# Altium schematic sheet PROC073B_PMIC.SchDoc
size 431 x 279 mm; Date: Not shown in title block; ApprovedBy: Not shown in title block; CheckedBy: Not shown in title block; Author: Not shown in title block; CompanyName: Not shown in title block; Engineer: Not shown in title block; Organization: Not shown in title block; Address1: Not shown in title block; Address2: Not shown in title block; Address3: Not shown in title block; Address4: Not shown in title block; DocumentNumber: 1; Revision: Use project parameter SCH_Rev; SheetNumber: 3; SheetTotal: 9; PageSetup: Record=PageOptions¦CenterHorizontal=True¦CenterVertical=True¦PrintScale=1.00¦XCorrection=1.00¦YCorrection=1.00¦PrintKind=0¦BorderSize=5000000¦LeftOffset=0¦BottomOffset=0¦Orientation=2¦PaperLength=1000¦PaperWidth=1000¦Scale=100¦PaperSource=15¦PrintQuality=600¦MediaType=1¦DitherType=10¦PaperKind=Letter¦PrintScaleMode=1
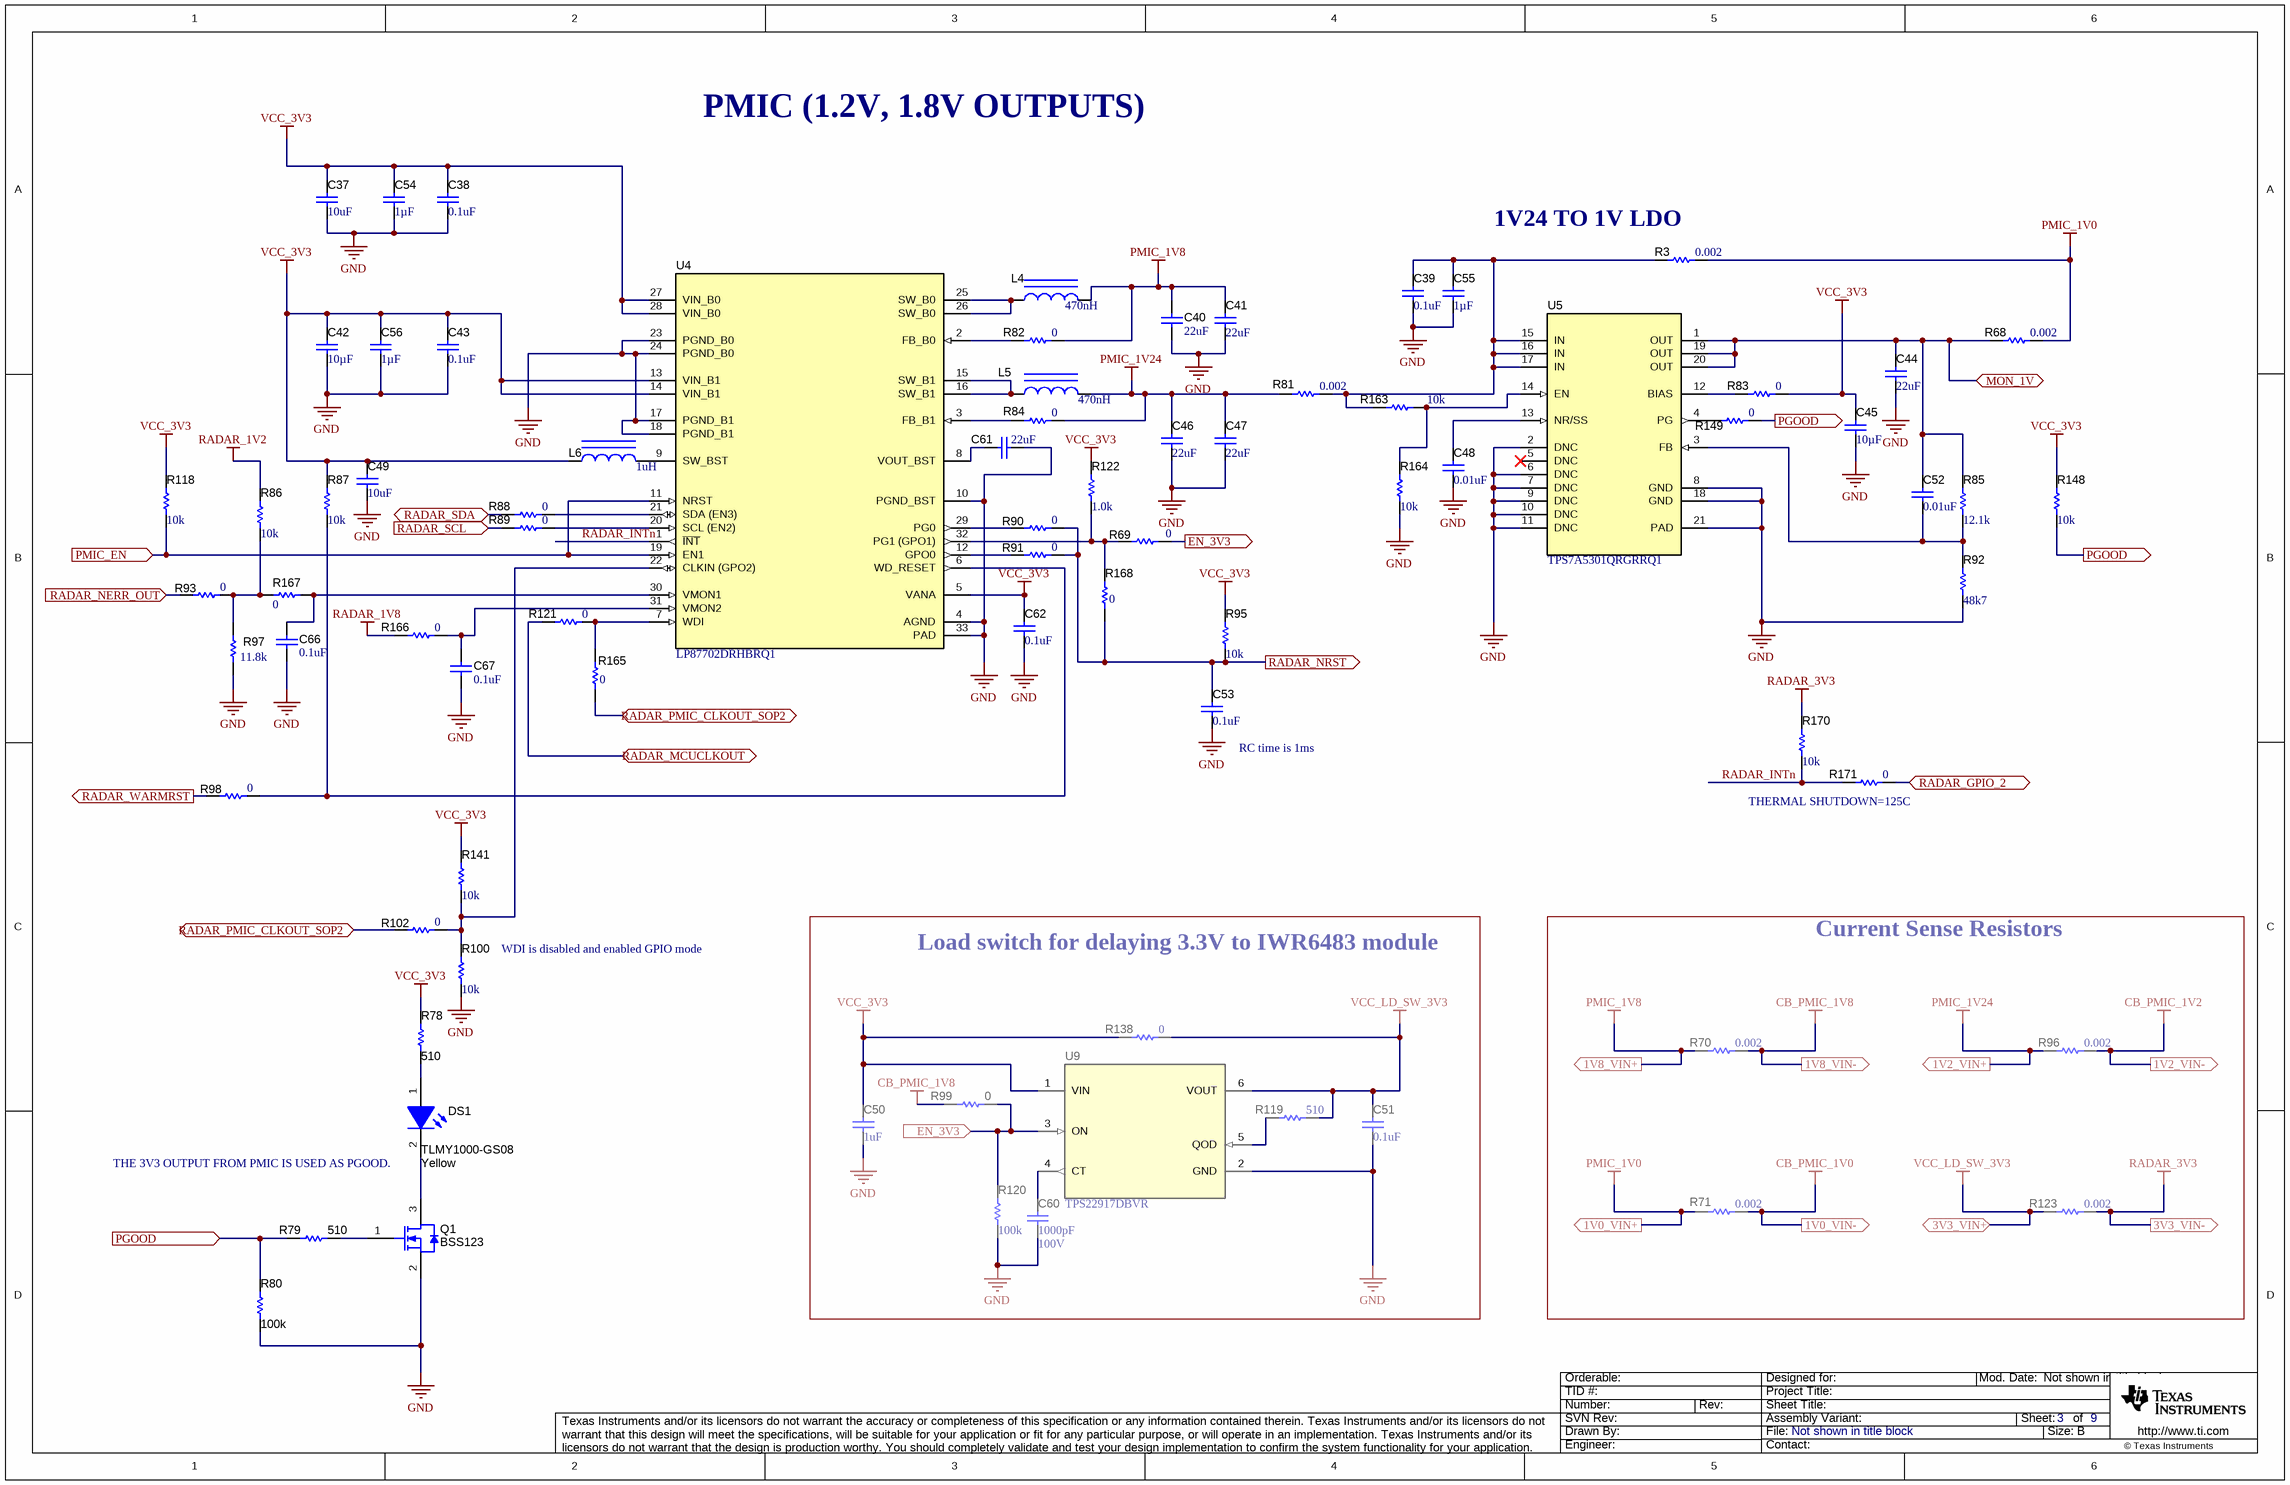
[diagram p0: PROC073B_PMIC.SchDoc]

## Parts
C37  value 10uF  [0805_HV]  (hidden comment: CL21B106KOQNNNE)
C38  value 0.1uF  [0402]  (hidden comment: 0402YC104KAT2A)
C39  ValueDisplayed: 0.1uF  [0402]  (hidden comment: 0402YC104KAT2A)
C40  ValueDisplayed: 22uF  [0805]  (hidden comment: GRM21BD70J226ME44L)
C41  ValueDisplayed: 22uF  [0805]  (hidden comment: GRM21BD70J226ME44L)
C42  Cap_F: 10µF  [0805_HV1]  (hidden comment: CL21B106KOQNNNE)
C43  value 0.1uF  [0402]  (hidden comment: 0402YC104KAT2A)
C44  ValueDisplayed: 22uF  [0805_HV]  (hidden comment: GRM21BD70J226ME44L)
C45  ValueDisplayed: 10µF  [0805_HV]  (hidden comment: GRM21BR71A106KA73L)
C46  ValueDisplayed: 22uF  [0805]  (hidden comment: GRM21BD70J226ME44L)
C47  ValueDisplayed: 22uF  [0805]  (hidden comment: GRM21BD70J226ME44L)
C48  ValueDisplayed: 0.01uF  [0402]  (hidden comment: GRM155R71C103KA01D)
C49  value 10uF  [0805_HV1]  (hidden comment: CL21B106KOQNNNE)
C50  ValueDisplayed: 1uF  [0603]  (hidden comment: CL10B105KQ8NNNC)
C51  ValueDisplayed: 0.1uF  [0603]  (hidden comment: GRM188R70J104KA01D)
C52  ValueDisplayed: 0.01uF  [0402]  (hidden comment: GRM155R71C103KA01D)
C53  ValueDisplayed: 0.1uF  [0402]  (hidden comment: 0402YC104KAT2A)
C54  ValueDisplayed: 1µF  [0402]  (hidden comment: CGB2A1X6S0J105K033BC)
C55  ValueDisplayed: 1µF  [0402]  (hidden comment: CGB2A1X6S0J105K033BC)
C56  ValueDisplayed: 1µF  [0402]  (hidden comment: CGB2A1X6S0J105K033BC)
C60  VDC_V: 100V  ValueDisplayed: 1000pF  [0402]  (hidden comment: CGA2B3X7S2A102K050BB)
C61  ValueDisplayed: 22uF  [0805_HV]  (hidden comment: GRM219R61C226ME15L)
C62  value 0.1uF  [0402]  (hidden comment: 0402YC104KAT2A)
C66  ValueDisplayed: 0.1uF  [0402]  (hidden comment: 0402YC104KAT2A)
C67  ValueDisplayed: 0.1uF  [0402]  (hidden comment: 0402YC104KAT2A)
DS1  TLMY1000-GS08  value Yellow  [TLMx1000_Yellow]
L4  value 470nH  [DFE252012P]  (hidden comment: DFE252012PD-R47M)
L5  value 470nH  [DFE252012P]  (hidden comment: DFE252012PD-R47M)
L6  value 1uH  [DFE252012P]  (hidden comment: DFE252012PD-1R0M)
Q1  BSS123  [SOT-23]
R3  ValueDisplayed: 0.002  [1206]  (hidden comment: PMR18EZPFV2L00)
R68  ValueDisplayed: 0.002  [1206]  (hidden comment: PMR18EZPFV2L00)
R69  value 0  [0402]  (hidden comment: CRCW04020000Z0ED)
R70  ValueDisplayed: 0.002  [1206]  (hidden comment: PMR18EZPFV2L00)
R71  ValueDisplayed: 0.002  [1206]  (hidden comment: PMR18EZPFV2L00)
R78  ValueDisplayed: 510  [0402L]  (hidden comment: ERJ-2GEJ511X)
R79  ValueDisplayed: 510  [0402L]  (hidden comment: ERJ-2GEJ511X)
R80  ValueDisplayed: 100k  [0402L]  (hidden comment: CRCW0402100KFKED)
R81  ValueDisplayed: 0.002  [1206]  (hidden comment: PMR18EZPFV2L00)
R82  value 0  [0402]  (hidden comment: CRCW04020000Z0ED)
R83  ValueDisplayed: 0  [0402]  (hidden comment: CRCW04020000Z0ED)
R84  value 0  [0402]  (hidden comment: CRCW04020000Z0ED)
R85  value 12.1k  [0402]  (hidden comment: CRCW040212K1FKED)
R86  value 10k  [0402]  (hidden comment: CRCW040210K0JNED)
R87  value 10k  [0402]  (hidden comment: CRCW040210K0JNED)
R88  ValueDisplayed: 0  [0201]  (hidden comment: CRCW02010000Z0ED)
R89  ValueDisplayed: 0  [0201]  (hidden comment: CRCW02010000Z0ED)
R90  value 0  [0402]  (hidden comment: CRCW04020000Z0ED)
R91  value 0  [0402]  (hidden comment: CRCW04020000Z0ED)
R92  Value_Code: 48k7  [0402]  (hidden comment: CRCW040248K7FKED)
R93  Res_ohm: 0  [0402]  (hidden comment: CRCW04020000Z0ED)
R95  value 10k  [0402]  (hidden comment: CRCW040210K0JNED)
R96  ValueDisplayed: 0.002  [1206]  (hidden comment: PMR18EZPFV2L00)
R97  ValueDisplayed: 11.8k  [0402]  (hidden comment: CRCW040211K8FKED)
R98  ValueDisplayed: 0  [0402]  (hidden comment: CRCW04020000Z0ED)
R99  ValueDisplayed: 0  [0603]  (hidden comment: MCT06030Z0000ZP500)
R100  value 10k  [0402]  (hidden comment: CRCW040210K0JNED)
R102  value 0  [0402]  (hidden comment: CRCW04020000Z0ED)
R118  value 10k  [0402]  (hidden comment: CRCW040210K0JNED)
R119  ValueDisplayed: 510  [0402]  (hidden comment: CRCW0402510RJNED)
R120  ValueDisplayed: 100k  [0402]  (hidden comment: ERJ-2RKF1003X)
R121  Res_ohm: 0  [0402]  (hidden comment: CRCW04020000Z0ED)
R122  value 1.0k  [0603]  (hidden comment: RC0603JR-071KL)
R123  ValueDisplayed: 0.002  [1206]  (hidden comment: PMR18EZPFV2L00)
R138  ValueDisplayed: 0  [0603]  (hidden comment: RCS06030000Z0EA)
R141  value 10k  [0402]  (hidden comment: CRCW040210K0JNED)
R148  value 10k  [0402]  (hidden comment: CRCW040210K0JNED)
R149  ValueDisplayed: 0  [0201]  (hidden comment: CRCW02010000Z0ED)
R163  value 10k  [0402]  (hidden comment: CRCW040210K0JNED)
R164  value 10k  [0402]  (hidden comment: CRCW040210K0JNED)
R165  Res_ohm: 0  [0402]  (hidden comment: CRCW04020000Z0ED)
R166  Res_ohm: 0  [0402]  (hidden comment: CRCW04020000Z0ED)
R167  Res_ohm: 0  [0402]  (hidden comment: CRCW04020000Z0ED)
R168  value 0  [0402]  (hidden comment: CRCW04020000Z0ED)
R170  value 10k  [0402]  (hidden comment: CRCW040210K0JNED)
R171  Res_ohm: 0  [0402]  (hidden comment: CRCW04020000Z0ED)
U4  LP87702DRHBRQ1  [RHB0032N]
U5  TPS7A5301QRGRRQ1  [RGR0020A]
U9  TPS22917DBVR  [DBV0006A_N]

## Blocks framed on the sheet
Load switch for delaying 3.3V to IWR6483 module: C50 C51 C60 R99 R119 R120 R138 U9
Current Sense Resistors: R70 R71 R96 R123

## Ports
1V0_VIN+ (out), 1V0_VIN- (out), 1V2_VIN+ (out), 1V2_VIN- (out), 1V8_VIN+ (out), 1V8_VIN- (out), 3V3_VIN+, 3V3_VIN- (out), EN_3V3 (in), EN_3V3 (out), MON_1V, PGOOD (in), PGOOD (out), PMIC_EN (in), RADAR_GPIO_2 (bidir), RADAR_MCUCLKOUT, RADAR_NERR_OUT (in), RADAR_NRST (out), RADAR_PMIC_CLKOUT_SOP2, RADAR_SCL (in), RADAR_SDA (bidir), RADAR_WARMRST (out)

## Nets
CB_PMIC_1V0: R71.2 ; port 1V0_VIN-
CB_PMIC_1V2: R96.2 ; port 1V2_VIN-
CB_PMIC_1V8: R70.2 R99.1 ; port 1V8_VIN-
GND: C37.1 C38.1 C39.1 C40.1 C41.2 C42.2 C43.1 C44.2 C45.1 C46.2 C47.2 C48.1 C49.2 C50.2 C51.2 C53.1 C54.2 C55.2 C56.2 C60.2 C61.2 C62.1 C66.1 C67.1 Q1.2(S) R80.1 R92.1 R97.2 R100.1 R120.1 R164.1 U4.4(AGND) U4.10(PGND_BST) U4.17(PGND_B1) U4.18(PGND_B1) U4.23(PGND_B0) U4.24(PGND_B0) U4.33(PAD) U5.2(DNC) U5.6(DNC) U5.7(DNC) U5.8(GND) U5.9(DNC) U5.10(DNC) U5.11(DNC) U5.18(GND) U5.21(PAD) U9.2(GND)
PMIC_1V0: R3.2 R68.2 R71.1 ; port 1V0_VIN+
PMIC_1V8: C40.2 C41.1 L4.2 R70.1 R82.2 ; port 1V8_VIN+
PMIC_1V24: C46.1 C47.1 L5.2 R81.1 R84.2 R96.1 ; port 1V2_VIN+
RADAR_1V2: R86.2
RADAR_1V8: R166.1
RADAR_3V3: R123.2 R170.2 ; port 3V3_VIN-
VCC_3V3: C37.2 C38.2 C42.1 C43.2 C45.2 C49.1 C50.1 C54.1 C56.1 C62.2 L6.1 R78.2 R83.2 R87.2 R95.2 R118.2 R122.1 R138.1 R141.2 R148.2 U4.5(VANA) U4.13(VIN_B1) U4.14(VIN_B1) U4.27(VIN_B0) U4.28(VIN_B0) U9.1(VIN)
VCC_LD_SW_3V3: C51.1 R119.1 R123.1 R138.2 U9.6(VOUT) ; port 3V3_VIN+
EN_3V3: R69.2 R99.2 R120.2 U9.3(ON) ; port EN_3V3
MON_1V: C44.1 C52.1 R68.1 R85.2 U5.1(OUT) U5.19(OUT) U5.20(OUT) ; port MON_1V
PGOOD: R79.1 R80.2 R148.1 R149.2 ; port PGOOD
PMIC_EN: R118.1 U4.11(NRST) U4.19(EN1) ; port PMIC_EN
RADAR_GPIO_2: R171.2 ; port RADAR_GPIO_2
RADAR_INTn: R170.1 R171.1 U4.1(~{INT})
RADAR_MCUCLKOUT: R121.1 ; port RADAR_MCUCLKOUT
RADAR_NERR_OUT: R93.1 ; port RADAR_NERR_OUT
RADAR_NRST: C53.2 R90.2 R91.2 R95.1 R168.1 ; port RADAR_NRST
RADAR_PMIC_CLKOUT_SOP2: R102.1 R165.1 ; port RADAR_PMIC_CLKOUT_SOP2
RADAR_SCL: R89.1 ; port RADAR_SCL
RADAR_SDA: R88.1 ; port RADAR_SDA
RADAR_WARMRST: R98.1 ; port RADAR_WARMRST
NetC39_2: C39.2 C55.1 R3.1 R81.2 R163.2 U5.15(IN) U5.16(IN) U5.17(IN)
NetC48_2: C48.2 U5.13(NR/SS)
NetC52_2: C52.2 R85.1 R92.2 U5.3(FB)
NetC60_1: C60.1 U9.4(CT)
NetC61_1: C61.1 U4.8(VOUT_BST)
NetC66_2: C66.2 R167.2 U4.30(VMON1)
NetC67_2: C67.2 R166.2 U4.31(VMON2)
NetDS1_1: DS1.1(A) R78.1
NetDS1_2: DS1.2(K) Q1.3(D)
NetL4_1: L4.1 U4.25(SW_B0) U4.26(SW_B0)
NetL5_1: L5.1 U4.15(SW_B1) U4.16(SW_B1)
NetL6_2: L6.2 U4.9(SW_BST)
NetQ1_1: Q1.1(G) R79.2
NetR69_1: R69.1 R122.2 R168.2 U4.32(PG1_(GPO1))
NetR82_1: R82.1 U4.2(FB_B0)
NetR83_1: R83.1 U5.12(BIAS)
NetR84_1: R84.1 U4.3(FB_B1)
NetR86_1: R86.1 R93.2 R97.1 R167.1
NetR87_1: R87.1 R98.2 U4.6(WD_RESET)
NetR88_2: R88.2 U4.21(SDA_(EN3))
NetR89_2: R89.2 U4.20(SCL_(EN2))
NetR90_1: R90.1 U4.29(PG0)
NetR91_1: R91.1 U4.12(GPO0)
NetR100_2: R100.2 R102.2 R141.1 U4.22(CLKIN_(GPO2))
NetR119_2: R119.2 U9.5(QOD)
NetR121_2: R121.2 R165.2 U4.7(WDI)
NetR149_1: R149.1 U5.4(PG)
NetR163_1: R163.1 R164.2 U5.14(EN)

Not connected (* = marked no-connect by the designer): U5 5(DNC)*

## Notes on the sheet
- PMIC (1.2V, 1.8V OUTPUTS)
- (near R3) 1V24 TO 1V LDO
- (near C53) RC time is 1ms
- (near R171) THERMAL SHUTDOWN=125C
- (near R100) WDI is disabled and enabled GPIO mode
- THE 3V3 OUTPUT FROM PMIC IS USED AS PGOOD.

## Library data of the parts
C37 C49 = CMP-0007995-2: CAP, CERM, 10 uF, 16 V, +/- 10%, X7R, 0805; Manufacturer: Samsung Electro-Mechanics; TaMin_C: -55°C; Polarized: N; SizeAreaWB_mm2: 6.75; Value1: Unknown; U/M: EA; TaMax_C: 125°C; SizeZ_mm: 1.45; SizeX_mm: 2; SizeY_mm: 1.25; Cap_Case: 0805; Value2: 16V; SizeArea_mm2: 2.5; CompType: Capacitor; Cap_F: 10µF; AEC Category: Q200
C38 C43 C62 = CMP-0006201-2: CAP, CERM, 0.1 uF, 16 V, +/- 10%, X7R, 0402; Manufacturer: AVX; TaMin_C: -55°C; Polarized: N; SizeAreaWB_mm2: 3; Value1: Unknown; U/M: EA; TaMax_C: 125°C; SizeZ_mm: 0.6; SizeX_mm: 1; SizeY_mm: 0.5; Value2: 16V; CompType: Capacitor; Cap_F: 100nF; AEC Category: Q200
C39 C53 C66 C67 = CMP-0006201-2: CAP, CERM, 0.1 uF, 16 V, +/- 10%, X7R, 0402; Manufacturer: AVX; TaMin_C: -55°C; Polarized: N; SizeAreaWB_mm2: 3; Value1: Unknown; U/M: EA; Value: 0.1uF; TaMax_C: 125°C; SizeZ_mm: 0.6; SizeX_mm: 1; SizeY_mm: 0.5; Value2: 16V; CompType: Capacitor; Cap_F: 100nF; AEC Category: Q200
C40 C41 C46 C47 = CMP-0008274-1: CAP, CERM, 22 uF, 6.3 V, +/- 20%, X7T, 0805; Manufacturer: MuRata; TaMin_C: -55°C; Polarized: N; SizeAreaWB_mm2: 6.75; Value1: Unknown; U/M: EA; Value: 22uF; TaMax_C: 125°C; SizeZ_mm: 1.45; SizeX_mm: 2; SizeY_mm: 1.25; Value2: 6.3V; SizeArea_mm2: 2.5; CompType: Capacitor; Cap_F: 22µF; AEC Category: Q200
C42 = CMP-0007995-2: CAP, CERM, 10 uF, 16 V, +/- 10%, X7R, 0805; Manufacturer: Samsung Electro-Mechanics; TaMin_C: -55°C; Polarized: N; SizeAreaWB_mm2: 6.75; Value1: Unknown; U/M: EA; Value: 10uF; TaMax_C: 125°C; SizeZ_mm: 1.45; SizeX_mm: 2; SizeY_mm: 1.25; Cap_Case: 0805; Value2: 16V; SizeArea_mm2: 2.5; CompType: Capacitor; AEC Category: Q200
C44 = CMP-0008274-1: CAP, CERM, 22 uF, 6.3 V, +/- 20%, X7T, 0805; Manufacturer: MuRata; TaMin_C: -55°C; Polarized: N; SizeAreaWB_mm2: 6.75; Value1: Unknown; U/M: EA; Value: 22uF; TaMax_C: 125°C; SizeZ_mm: 1.45; SizeX_mm: 2; SizeY_mm: 1.25; Cap_Case: 0805; Value2: 6.3V; SizeArea_mm2: 2.5; CompType: Capacitor; Cap_F: 22µF; AEC Category: Q200
C45 = CMP-0081849-1: CAP, CERM, 10 µF,  V,+/- 10%, X7R, 0805; Manufacturer: MuRata; TaMin_C: -55°C; Polarized: N; Green_Lifecycle: Active; SizeAreaWB_mm2: 6.75; Green_REACh: Passed; U/M: EA; Value: 10uF; TaMax_C: 125°C; SizeZ_mm: 1.45; SizeX_mm: 2; SizeY_mm: 1.25; Cap_Case: 0805; SizeArea_mm2: 2.5; AEC Category: Q200
C48 = CMP-0006639-2: CAP, CERM, 0.01 uF, 16 V, +/- 10%, X7R, 0402; Manufacturer: MuRata; TaMin_C: -55°C; Polarized: N; SizeAreaWB_mm2: 3; Value1: Unknown; U/M: EA; Value: 0.01uF; TaMax_C: 125°C; SizeZ_mm: 0.6; SizeX_mm: 1; SizeY_mm: 0.5; Value2: 16V; CompType: Capacitor; Cap_F: 10nF; AEC Category: Q200
C50 = CMP-0007111-4: CAP, CERM, 1 uF, 6.3 V, +/- 10%, X7R, 0603; Manufacturer: Samsung Electro-Mechanics; TaMin_C: -55°C; Polarized: N; SizeAreaWB_mm2: 4.68; Value1: Unknown; U/M: EA; Value: 1uF; TaMax_C: 125°C; SizeZ_mm: 1; SizeX_mm: 1.6; SizeY_mm: 0.8; Value2: 6.3V; SizeArea_mm2: 1.28; CompType: Capacitor; Cap_F: 1µF; AEC Category: Q200
C51 = CMP-0007359-4: CAP, CERM, 0.1 uF, 6.3 V, +/- 10%, X7R, 0603; Manufacturer: MuRata; TaMin_C: -55°C; Polarized: N; SizeAreaWB_mm2: 4.68; Value1: Unknown; U/M: EA; Value: 0.1uF; TaMax_C: 125°C; SizeZ_mm: 1; SizeX_mm: 1.6; SizeY_mm: 0.8; Value2: 6.3V; SizeArea_mm2: 1.28; CompType: Capacitor; Cap_F: 100nF; AEC Category: Q200
C52 = CMP-0006639-2: CAP, CERM, 0.01 uF, 16 V, +/- 10%, X7R, 0402; Manufacturer: MuRata; TaMin_C: -55°C; Polarized: N; SizeAreaWB_mm2: 3; Value1: Unknown; U/M: EA; Value: 0.01uF; TaMax_C: 125°C; SizeZ_mm: 0.6; SizeX_mm: 1; SizeY_mm: 0.5; Value2: 16V; CompType: Capacitor; Cap_F: 10nF; AEC Category: Q200; INSTALLATION: DNP
C54-C56 = CMP-0081763-1: CAP, CERM, 1 µF, 6.3 V,+/- 10%, X6S, 0402; Manufacturer: TDK; TaMin_C: -55°C; Polarized: N; SizeAreaWB_mm2: 3; U/M: EA; Value: 1uF; TaMax_C: 105°C; SizeZ_mm: 0.6; SizeX_mm: 1; SizeY_mm: 0.5; Value2: 6.3V; CompType: Capacitor; AEC Category: Q200
C60 = CMP-0006332-2: CAP, CERM, 1000 pF, 100 V, +/- 10%, X7S, AEC-Q200 Grade 1, 0402; Manufacturer: TDK; TaMin_C: -55°C; ESR_ohm: 2.71151; Polarized: N; SizeAreaWB_mm2: 3; Value1: 2.71151 ohm; U/M: EA; Value: 1000pF; TaMax_C: 125°C; SizeZ_mm: 0.6; SizeX_mm: 1; SizeY_mm: 0.5; AEC Qualified: Y; Cap_F: 1nF; IRMS_A: 2.64589dA; AEC Category: Q200
C61 = CMP-0008203-2: CAP, CERM, 22 uF, 16 V, +/- 20%, X5R, 0805; Manufacturer: MuRata; TaMin_C: -55°C; Polarized: N; SizeAreaWB_mm2: 6.75; Value1: Unknown; U/M: EA; Value: 22uF; TaMax_C: 85°C; SizeZ_mm: 1.45; SizeX_mm: 2; SizeY_mm: 1.25; Cap_Case: 0805; Value2: 16V; SizeArea_mm2: 2.5; CompType: Capacitor; Cap_F: 22µF; AEC Category: Q200
DS1 = CMP-0078196-1: LED, Yellow, SMD; Manufacturer: Vishay-Semiconductor; Tjmax_C: 120°C; SizeAreaWB_mm2: 4.68; Vr_V: 6V; Power_TotalModule: 40mW; Angle: 160; SizeArea_mm2: 1.28; Ir_A: 10µA; SizeZ_mm: 0.65; Io_A: 2mA; Vf_V: 1.8V; SizeY_mm: 0.8; U/M: EA; Value1: .04W; SizeX_mm: 1.6; Type: AlInGaP
L4 L5 = CMP-0058944-1: Inductor, Shielded, 470 nH, 4.7 A, 0.021 ohm, SMD; Manufacturer: MuRata Toko; Isat: 6.1A @ 30% inductance drop; Irms: 4.7A @ 40C rise; SizeAreaWB_mm2: 10.5; DCR_ohm: 0.021; Imax_A: 4.7A; SizeZ_mm: 1.2; SizeX_mm: 2.5; SizeY_mm: 2; SizeArea_mm2: 5; AEC Category: Q200
L6 = CMP-0058938-1: Inductor, Shielded, 1 uH, 3.8 A, 0.035 ohm, AEC-Q200 Grade 1, SMD; Manufacturer: MuRata Toko; Isat: 4.5A @ 30% inductance drop; Irms: 3.8A @ 40C rise; SizeAreaWB_mm2: 10.5; DCR_ohm: 0.035; Imax_A: 3.8A; SizeZ_mm: 1.2; SizeX_mm: 2.5; SizeY_mm: 2; SizeArea_mm2: 5; Ind_H: 1µH; AEC Qualified: Y; AEC Grade: 1; AEC Category: Q200
Q1 = CMP-0000947-2: MOSFET, N-CH, 100 V, 0.17 A, SOT-23; Alternate Manufacturer: None; Manufacturer: Fairchild Semiconductor; SizeZ_mm: 1.1; ChType: N; Value2: 1.8 nC; Value1: 1; VdsMax_V: 100V; SizeX_mm: 2.5; SizeY_mm: 3; Vgs_V: 20V; Value: 100V; Rdson45_ohm: 10; SizeArea_mm2: 7.5; AEC Category: Q101; IdsMax_A: 1.7dA; SizeAreaWB_mm2: 14; U/M: EA; QgTyp_nC: 1.8
R3 = CMP-0081623-1: RES, 0.002, 1%, 1 W, AEC-Q200 Grade 0, 1206; Manufacturer: Rohm; Value_Code: 2L000; SizeAreaWB_mm2: 10.92; SizeArea_mm2: 5.12; AEC Qualified: Y; AEC Category: Q200; Res_ohm: 2m; Value: 0.002; SizeZ_mm: 1.35; Green_REACh: Incomplete; TempCo: 100 ppm/C; AEC Grade: 0; Power_W: 1W; SizeY_mm: 1.6; Green_Lifecycle: Active; CompType: Resistor; SizeX_mm: 3.2; INSTALLATION: DNP
R68 R70 R71 R81 R96 R123 = CMP-0081623-1: RES, 0.002, 1%, 1 W, AEC-Q200 Grade 0, 1206; Manufacturer: Rohm; Value_Code: 2L000; SizeAreaWB_mm2: 10.92; SizeArea_mm2: 5.12; AEC Qualified: Y; AEC Category: Q200; Res_ohm: 2m; Value: 0.002; SizeZ_mm: 1.35; Green_REACh: Incomplete; TempCo: 100 ppm/C; AEC Grade: 0; Power_W: 1W; SizeY_mm: 1.6; Green_Lifecycle: Active; SizeX_mm: 3.2
R69 R90 R102 = CMP-0026822-3: RES, 0, 5%, 0.063 W, AEC-Q200 Grade 0, 0402; Manufacturer: Vishay-Dale; Power_W: 63mW; TempCo: 200 ppm/C; Value_Code: 0000; EIA_Code: E24; SizeX_mm: 1; SizeY_mm: 0.5; SizeZ_mm: 0.6; Value2: 0.063W; CompType: Resistor; AEC Qualified: Y; VDC_V: 50V; AEC Category: Q200; INSTALLATION: DNP
R78 R79 = CMP-0078212-1: RES, 510, 5%, 0.1 W, AEC-Q200 Grade 0, 0402; Manufacturer: Panasonic; Value_Code: 510R; SizeArea_mm2: 0.5; AEC Qualified: Y; AEC Category: Q200; Value: 510; SizeZ_mm: 0.6; EIA_Code: E24; TempCo: 200 ppm/C; AEC Grade: 0; Power_W: 100mW; VDC_V: 50V; Value2: 0.1W; U/M: EA; SizeX_mm: 1
R80 = CMP-0025950-2: RES, 100 k, 1%, 0.063 W, 0402; Manufacturer: Vishay-Dale; Power_W: 63mW; TempCo: 100 ppm/C; U/M: EA; Value: 100k; EIA_Code: E96; SizeX_mm: 1; SizeY_mm: 0.5; SizeZ_mm: 0.6; Value2: 0.063W; VDC_V: 50V; AEC Category: Q200
R82 R84 R91 R168 = CMP-0026822-3: RES, 0, 5%, 0.063 W, AEC-Q200 Grade 0, 0402; Manufacturer: Vishay-Dale; Power_W: 63mW; TempCo: 200 ppm/C; Value_Code: 0000; EIA_Code: E24; SizeX_mm: 1; SizeY_mm: 0.5; SizeZ_mm: 0.6; Value2: 0.063W; CompType: Resistor; AEC Qualified: Y; VDC_V: 50V; AEC Category: Q200
R83 R121 R166 R171 = CMP-0026822-3: RES, 0, 5%, 0.063 W, AEC-Q200 Grade 0, 0402; Manufacturer: Vishay-Dale; Power_W: 63mW; TempCo: 200 ppm/C; Value_Code: 0000; Value: 0; EIA_Code: E24; SizeX_mm: 1; SizeY_mm: 0.5; SizeZ_mm: 0.6; Value2: 0.063W; CompType: Resistor; AEC Qualified: Y; VDC_V: 50V; AEC Category: Q200
R85 = CMP-0025991-3: RES, 12.1 k, 1%, 0.063 W, AEC-Q200 Grade 0, 0402; Manufacturer: Vishay-Dale; Power_W: 63mW; TempCo: 100 ppm/C; Value_Code: 12k1; EIA_Code: E96; SizeX_mm: 1; SizeY_mm: 0.5; SizeZ_mm: 0.6; Value2: 0.063W; CompType: Resistor; AEC Qualified: Y; VDC_V: 50V; AEC Category: Q200; AEC Grade: 0
R86 R87 R118 R141 R148 R163 R170 = CMP-0026825-5: RES, 10 k, 5%, 0.063 W, AEC-Q200 Grade 0, 0402; Manufacturer: Vishay-Dale; Power_W: 63mW; TempCo: 200 ppm/C; Value_Code: 10k0; EIA_Code: E24; SizeX_mm: 1; SizeY_mm: 0.5; SizeZ_mm: 0.6; Value2: 0.063W; CompType: Resistor; AEC Qualified: Y; VDC_V: 50V; AEC Category: Q200; AEC Grade: 0
R88 R89 R149 = CMP-0027008-4: RES, 0, 5%, 0.05 W, 0201; Manufacturer: Vishay-Dale; Power_W: 50mW; TempCo: ppm/C; Value_Code: 0000; Value: 0; EIA_Code: E24; SizeX_mm: 0.6; SizeY_mm: 0.3; SizeZ_mm: 0.26; Value2: 0.05W; SizeArea_mm2: 0.18; AEC Qualified: N; AEC Category: Q200
R92 = CMP-0026399-2: RES, 48.7 k, 1%, 0.063 W, AEC-Q200 Grade 0, 0402; Manufacturer: Vishay-Dale; Power_W: 63mW; TempCo: 100 ppm/C; Value: 48.7k; EIA_Code: E96; SizeX_mm: 1; SizeY_mm: 0.5; SizeZ_mm: 0.6; Value2: 0.063W; CompType: Resistor; AEC Qualified: Y; VDC_V: 50V; AEC Category: Q200; AEC Grade: 0
R93 R98 R165 R167 = CMP-0026822-3: RES, 0, 5%, 0.063 W, AEC-Q200 Grade 0, 0402; Manufacturer: Vishay-Dale; Power_W: 63mW; TempCo: 200 ppm/C; Value_Code: 0000; Value: 0; EIA_Code: E24; SizeX_mm: 1; SizeY_mm: 0.5; SizeZ_mm: 0.6; Value2: 0.063W; CompType: Resistor; AEC Qualified: Y; VDC_V: 50V; AEC Category: Q200; INSTALLATION: DNP
R95 R100 R164 = CMP-0026825-5: RES, 10 k, 5%, 0.063 W, AEC-Q200 Grade 0, 0402; Manufacturer: Vishay-Dale; Power_W: 63mW; TempCo: 200 ppm/C; Value_Code: 10k0; EIA_Code: E24; SizeX_mm: 1; SizeY_mm: 0.5; SizeZ_mm: 0.6; Value2: 0.063W; CompType: Resistor; AEC Qualified: Y; VDC_V: 50V; AEC Category: Q200; AEC Grade: 0; INSTALLATION: DNP
R97 = CMP-0025978-3: RES, 11.8 k, 1%, 0.063 W, AEC-Q200 Grade 0, 0402; Manufacturer: Vishay-Dale; Power_W: 63mW; TempCo: 100 ppm/C; Value_Code: 11k8; Value: 11.8k; EIA_Code: E96; SizeX_mm: 1; SizeY_mm: 0.5; SizeZ_mm: 0.6; Value2: 0.063W; CompType: Resistor; AEC Qualified: Y; VDC_V: 50V; AEC Category: Q200; AEC Grade: 0
R99 = CMP-0025884-3: RES, 0, 5%, 0.125 W, 0603; Manufacturer: Vishay/Beyschlag; Power_W: 125mW; TempCo: ppm/C; Value_Code: 0000; U/M: EA; Value: 0; EIA_Code: E24; SizeX_mm: 1.6; SizeY_mm: 0.8; SizeZ_mm: 1; Value2: 0.125W; SizeArea_mm2: 1.28; CompType: Resistor; AEC Qualified: N; AEC Category: Q200; INSTALATION: DNP
R119 = CMP-0026944-3: RES, 510, 5%, 0.063 W, AEC-Q200 Grade 0, 0402; Manufacturer: Vishay-Dale; Power_W: 63mW; TempCo: 200 ppm/C; Value_Code: 510R; Value: 510; EIA_Code: E24; SizeX_mm: 1; SizeY_mm: 0.5; SizeZ_mm: 0.6; Value2: 0.063W; AEC Qualified: Y; VDC_V: 50V; AEC Category: Q200; AEC Grade: 0
R120 = CMP-0026659-1: RES, 100 k, 1%, 0.1 W, 0402; Manufacturer: Panasonic; Power_W: 100mW; TempCo: 100 ppm/C; U/M: EA; Value: 100k; EIA_Code: E96; SizeX_mm: 1; SizeY_mm: 0.5; SizeZ_mm: 0.6; Value2: 0.1W; VDC_V: 50V; AEC Category: Q200
R122 = CMP-0025899-5: RES, 1.0 k, 5%, 0.1 W, 0603; Manufacturer: Yageo; Power_W: 100mW; TempCo: 100 ppm/C; Value_Code: 1k00; EIA_Code: E24; Res_ohm: 1k; SizeX_mm: 1.6; SizeY_mm: 0.8; SizeZ_mm: 1; Value2: 0.1W; SizeArea_mm2: 1.28; CompType: Resistor; AEC Qualified: N; VDC_V: 75V; AEC Category: Q200; SizeAreaWB_mm2: 4.68; INSTALLATION: DNP
R138 = CMP-0081973-1: RES, 0, 0%, 0.25 W, AEC-Q200 Grade 0, 0603; Manufacturer: Vishay-Dale; SizeAreaWB_mm2: 4.68; SizeArea_mm2: 1.28; AEC Qualified: Y; AEC Category: Q200; Value: 0; SizeZ_mm: 1; SizeY_mm: 0.8; Power_W: 250mW; Value2: 0.25W; CompType: Resistor; SizeX_mm: 1.6; INSTALLATION: DNP
U4 = CMP-0078631-1: Boost and Dual Buck Regulators With Diagnostic Functions, RHB0032N (VQFN-32); Manufacturer: Texas Instruments; SizeZ_mm: 0.9; SizeX_mm: 5; AEC Category: Q200; AEC Qualified: Y; SizeArea_mm2: 25; CompType: IC; SizeAreaWB_mm2: 49
U5 = CMP-0077268-2: Automotive 3A High-Accuracy Low-Noise Low-Dropout (LDO) Voltage Regulator, RGR0020A (VQFN-20); Manufacturer: Texas Instruments; SizeAreaWB_mm2: 20.25; SizeZ_mm: 1.0; SizeX_mm: 3.5; SizeArea_mm2: 12.25; CompType: IC; AEC Qualified: Y; AEC Category: Q200
U9 = CMP-0077265-1: 5.5-V, 2-A, 80 mohm Low Leakage Load Switch with RCB and Programmable Rise Time, DBV0006A (SOT-23-6); Alternate PartNumber: TPS22917DBVT; Alternate Manufacturer: Texas Instruments; SizeAreaWB_mm2: 14.82; SizeZ_mm: 1.45; SizeX_mm: 2.8; SizeY_mm: 2.9; SizeArea_mm2: 8.12; CompType: IC; AEC Qualified: N; AEC Category: Q200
